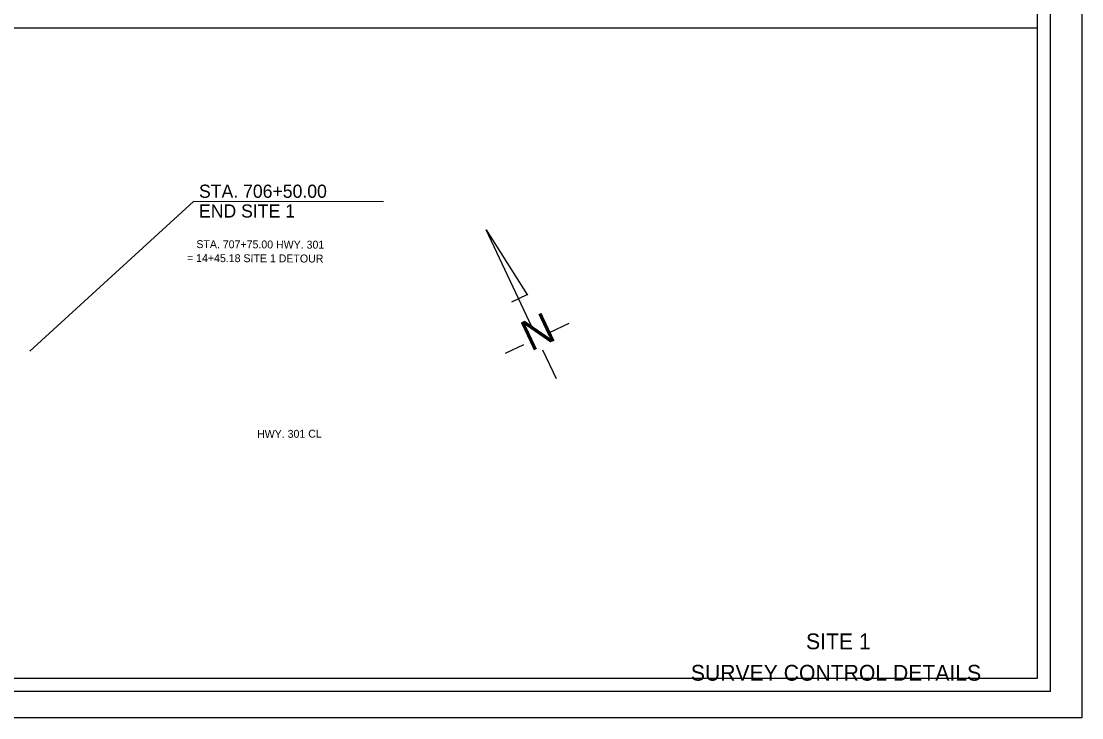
# Model space of a CAD drawing. Extents: x 818639 to 819473, y 1805980 to 1806194.
# Drawn here: x 818811.6 to 818972.5, y 1805980.3 to 1806086 of the extents above; entities that cross this region are included whole.
import ezdxf

# ---------------------------------------------------------------- set-up
doc = ezdxf.new("R2010")
doc.units = 0
for name, color, linetype in [('Default', 7, 'Continuous'), ('JOB Text', 7, 'Continuous'), ('R_Border', 7, 'Continuous'), ('R_Border Title', 7, 'Continuous'), ('R_Detour Annot Point', 7, 'Continuous'), ('R_Horz Alg Annot Point', 7, 'Continuous'), ('R_No Plot', 7, 'Continuous')]:
    doc.layers.add(name, color=color, linetype=linetype)

msp = doc.modelspace()

# ---------------------------------------------------------------- linework, layer by layer
at = {"layer": 'Default'}
for p, q in [((818882.15, 1806054.38), (818888.44, 1806044.48)), ((818889.1, 1806039.67), (818882.15, 1806054.38)), ((818886.07, 1806043.45), (818888.4, 1806044.56)), ((818891.78, 1806038.81), (818894.76, 1806040.22)), ((818885.08, 1806035.65), (818887.87, 1806036.96)), ((818892.83, 1806031.77), (818890.78, 1806036.1))]:
    msp.add_line(p, q, dxfattribs=at)
at = {"layer": 'JOB Text'}
msp.add_lwpolyline([(818866.6, 1806058.65), (818837.79, 1806058.67), (818812.95, 1806035.95)], dxfattribs=at)
at = {"layer": 'R_Border'}
for q in [(818967.78, 1806189.77), (818651.6, 1805984.31)]:
    msp.add_line((818967.78, 1805984.31), q, dxfattribs=at)
at = {"layer": 'R_No Plot'}
for points in [[(818639.19, 1806193.67), (818972.53, 1806193.67), (818972.53, 1805980.33), (818639.19, 1805980.33)], [(818653.6, 1806187.77), (818903.14, 1806187.77), (818903.14, 1806177.89), (818920.68, 1806177.89), (818944.78, 1806177.89), (818944.78, 1806155.56), (818965.78, 1806155.56), (818965.78, 1805986.31), (818653.6, 1805986.31)], [(818653.6, 1806085.04), (818965.78, 1806085.04), (818965.78, 1805986.31), (818653.6, 1805986.31)]]:
    msp.add_lwpolyline(points, close=True, dxfattribs=at)

# ---------------------------------------------------------------- texts
at = {"layer": 'Default'}
msp.add_text('N', height=4.65, rotation=25.2735, dxfattribs=at).set_placement((818888.94, 1806035.88))
at = {"layer": 'JOB Text'}
for s, p in [('STA. 706+50.00', (818838.6, 1806059.24)), ('END SITE 1    ', (818838.6, 1806056.24))]:
    msp.add_text(s, height=2, dxfattribs=at).set_placement(p)
at = {"layer": 'R_Border'}
msp.add_text('SITE 1', height=2.4, dxfattribs=at).set_placement((818930.7, 1805990.73))
at = {"layer": 'R_Border Title'}
msp.add_text('SURVEY CONTROL DETAILS', height=2.4, dxfattribs=at).set_placement((818913.22, 1805985.96))
at = {"layer": 'R_Detour Annot Point'}
for s, p in [('STA. 707+75.00 HWY. 301', (818838.2, 1806051.61)), ('= 14+45.18 SITE 1 DETOUR', (818836.78, 1806049.51))]:
    msp.add_text(s, height=1.2, rotation=359.7416, dxfattribs=at).set_placement(p)
at = {"layer": 'R_Horz Alg Annot Point'}
msp.add_text('HWY. 301 CL', height=1.2, rotation=0.3489, dxfattribs=at).set_placement((818847.42, 1806022.79))

doc.saveas('drawing.dxf')
